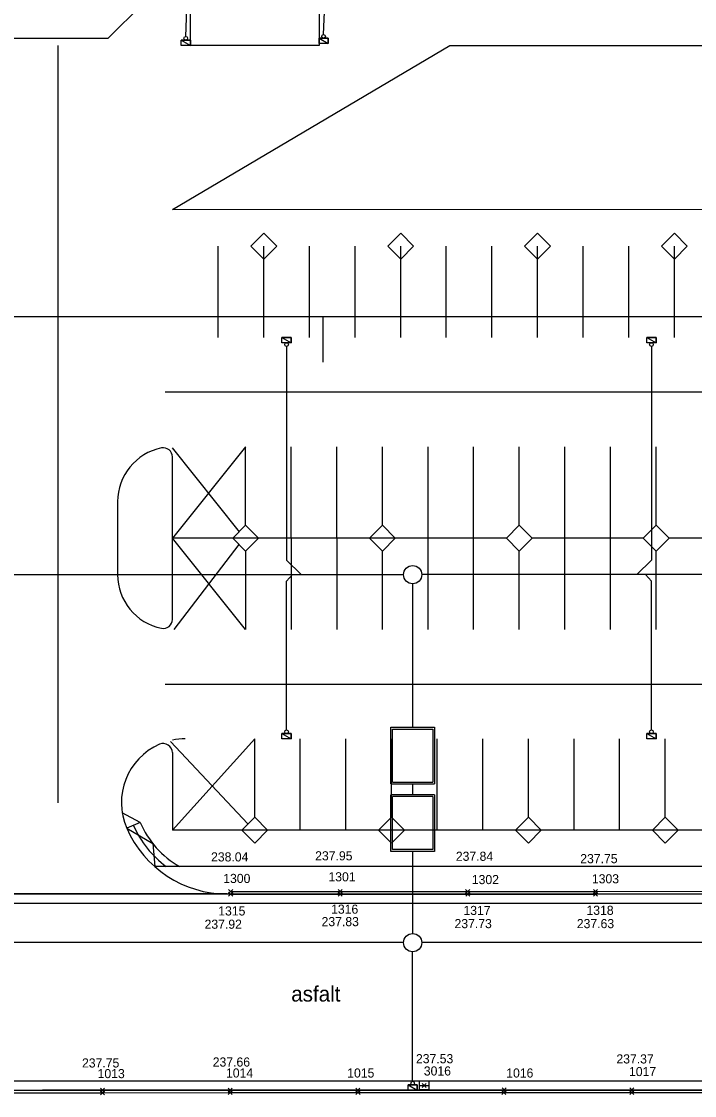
# Model space of a CAD drawing. Extents: x -264205 to -263615, y -1242401 to -1242031.
# Drawn here: x -263925.3 to -263888.5, y -1242312.5 to -1242253.7 of the extents above; entities that cross this region are included whole.
import ezdxf

# ---------------------------------------------------------------- set-up
doc = ezdxf.new("R2010")
doc.units = 0
for name, color, linetype in [('BODY_SYMBOL A CISLO_2-1', 7, 'Continuous'), ('BODY_VYSKA_2-1', 7, 'Continuous'), ('KOORDINACNA_SITUACIA_DSP', 7, 'Continuous'), ('POPIS', 7, 'Continuous'), ('PROJEKT_DRS_TDZ_VODOROVNE', 7, 'Continuous'), ('RAM_NA_TLAC_1-250_SITUACIA_2-1', 7, 'Continuous'), ('ROZHRANIE_SO_20-1_a_20-2', 7, 'Continuous'), ('SO_20-1_OBRUBNIKY_DOLNA_HRANA', 7, 'Continuous'), ('SO_20-1_OBRUBNIKY_HORNA_HRANA', 7, 'Continuous'), ('SO_20-1_UV', 7, 'Continuous')]:
    doc.layers.add(name, color=color, linetype=linetype)

msp = doc.modelspace()

# ---------------------------------------------------------------- linework, layer by layer
at = {"layer": 'BODY_SYMBOL A CISLO_2-1'}
for p, q in [((-263913.995, -1242301.454), (-263913.774, -1242301.234)), ((-263913.774, -1242301.454), (-263913.995, -1242301.234)), ((-263913.995, -1242301.6), (-263913.774, -1242301.379)), ((-263913.774, -1242301.6), (-263913.995, -1242301.379)), ((-263908.003, -1242301.454), (-263907.782, -1242301.232)), ((-263907.782, -1242301.454), (-263908.003, -1242301.232)), ((-263908.003, -1242301.6), (-263907.782, -1242301.379)), ((-263907.782, -1242301.6), (-263908.003, -1242301.379)), ((-263901.007, -1242301.454), (-263900.785, -1242301.234)), ((-263900.785, -1242301.454), (-263901.007, -1242301.234)), ((-263901.001, -1242301.599), (-263900.78, -1242301.377)), ((-263900.78, -1242301.599), (-263901.001, -1242301.377)), ((-263894.008, -1242301.593), (-263893.787, -1242301.373)), ((-263893.787, -1242301.593), (-263894.008, -1242301.373)), ((-263894.006, -1242301.448), (-263893.785, -1242301.228)), ((-263893.785, -1242301.448), (-263894.006, -1242301.228)), ((-263903.389, -1242312.082), (-263903.168, -1242311.86)), ((-263903.168, -1242312.082), (-263903.389, -1242311.86)), ((-263921.02, -1242312.345), (-263920.799, -1242312.123)), ((-263920.799, -1242312.345), (-263921.02, -1242312.123)), ((-263921.019, -1242312.488), (-263920.799, -1242312.268)), ((-263920.799, -1242312.488), (-263921.019, -1242312.268)), ((-263914.025, -1242312.336), (-263913.804, -1242312.115)), ((-263913.804, -1242312.336), (-263914.025, -1242312.115)), ((-263914.02, -1242312.475), (-263913.799, -1242312.255)), ((-263913.799, -1242312.475), (-263914.02, -1242312.255)), ((-263907.023, -1242312.338), (-263906.802, -1242312.117)), ((-263906.802, -1242312.338), (-263907.023, -1242312.117)), ((-263907.018, -1242312.468), (-263906.796, -1242312.248)), ((-263906.796, -1242312.468), (-263907.018, -1242312.248)), ((-263899.02, -1242312.468), (-263898.799, -1242312.247)), ((-263898.799, -1242312.468), (-263899.02, -1242312.247)), ((-263899.007, -1242312.319), (-263898.785, -1242312.097)), ((-263898.785, -1242312.319), (-263899.007, -1242312.097)), ((-263892.013, -1242312.465), (-263891.791, -1242312.244)), ((-263891.791, -1242312.465), (-263892.013, -1242312.244)), ((-263892.011, -1242312.319), (-263891.79, -1242312.099)), ((-263891.79, -1242312.319), (-263892.011, -1242312.099))]:
    msp.add_line(p, q, dxfattribs=at)
at = {"layer": 'KOORDINACNA_SITUACIA_DSP'}
for p, q in [((-263916.093, -1242254.982), (-263916.093, -1242250.458)), ((-263909.043, -1242250.458), (-263909.043, -1242254.982)), ((-263916.339, -1242254.492), (-263916.265, -1242252.443)), ((-263920.595, -1242254.592), (-263918.723, -1242252.72)), ((-263908.789, -1242254.387), (-263908.729, -1242252.715)), ((-263929.73, -1242254.592), (-263920.595, -1242254.592)), ((-263916.593, -1242254.692), (-263916.093, -1242254.692)), ((-263916.593, -1242254.982), (-263916.593, -1242254.692)), ((-263916.593, -1242254.692), (-263916.093, -1242254.982)), ((-263916.593, -1242254.692), (-263916.093, -1242254.982)), ((-263916.093, -1242254.692), (-263916.593, -1242254.692)), ((-263916.093, -1242254.982), (-263916.593, -1242254.982)), ((-263916.093, -1242254.692), (-263916.093, -1242254.982)), ((-263916.093, -1242254.982), (-263916.093, -1242254.692)), ((-263909.043, -1242254.982), (-263916.093, -1242254.982)), ((-263909.043, -1242254.587), (-263908.543, -1242254.587)), ((-263909.043, -1242254.877), (-263909.043, -1242254.587)), ((-263909.043, -1242254.587), (-263908.543, -1242254.877)), ((-263909.043, -1242254.587), (-263908.543, -1242254.877)), ((-263908.543, -1242254.587), (-263909.043, -1242254.587)), ((-263908.543, -1242254.877), (-263909.043, -1242254.877)), ((-263908.543, -1242254.587), (-263908.543, -1242254.877)), ((-263908.543, -1242254.877), (-263908.543, -1242254.587)), ((-263911.074, -1242270.983), (-263910.574, -1242270.983)), ((-263911.074, -1242271.273), (-263911.074, -1242270.983)), ((-263911.074, -1242270.983), (-263910.574, -1242271.273)), ((-263911.074, -1242270.983), (-263910.574, -1242271.273)), ((-263910.574, -1242270.983), (-263911.074, -1242270.983)), ((-263910.574, -1242271.273), (-263911.074, -1242271.273)), ((-263910.574, -1242270.983), (-263910.574, -1242271.273)), ((-263910.574, -1242271.273), (-263910.574, -1242270.983)), ((-263891.074, -1242270.983), (-263890.574, -1242270.983)), ((-263891.074, -1242271.273), (-263891.074, -1242270.983)), ((-263891.074, -1242270.983), (-263890.574, -1242271.273)), ((-263891.074, -1242270.983), (-263890.574, -1242271.273)), ((-263890.574, -1242270.983), (-263891.074, -1242270.983)), ((-263890.574, -1242271.273), (-263891.074, -1242271.273)), ((-263890.574, -1242270.983), (-263890.574, -1242271.273)), ((-263890.574, -1242271.273), (-263890.574, -1242270.983)), ((-263910.824, -1242271.473), (-263910.824, -1242283.187)), ((-263890.824, -1242271.473), (-263890.824, -1242283.187)), ((-263917.08, -1242286.432), (-263917.08, -1242277.533)), ((-263920.08, -1242279.982), (-263920.08, -1242283.982)), ((-263910.824, -1242283.187), (-263910.029, -1242283.982)), ((-263890.824, -1242283.187), (-263891.619, -1242283.982)), ((-263946.608, -1242283.982), (-263908.955, -1242283.982)), ((-263946.608, -1242283.982), (-263904.413, -1242283.982)), ((-263910.824, -1242284.343), (-263910.499, -1242283.982)), ((-263910.824, -1242292.492), (-263910.824, -1242284.343)), ((-263871.324, -1242283.982), (-263903.413, -1242283.982)), ((-263890.824, -1242284.343), (-263891.149, -1242283.982)), ((-263890.824, -1242292.492), (-263890.824, -1242284.343)), ((-263903.913, -1242284.482), (-263903.913, -1242292.347)), ((-263905.113, -1242292.347), (-263902.713, -1242292.347)), ((-263905.113, -1242295.447), (-263905.113, -1242292.347)), ((-263905.013, -1242292.447), (-263902.813, -1242292.447)), ((-263905.013, -1242295.347), (-263905.013, -1242292.447)), ((-263902.813, -1242292.447), (-263902.813, -1242295.347)), ((-263902.713, -1242292.347), (-263902.713, -1242295.447)), ((-263911.074, -1242292.692), (-263910.574, -1242292.692)), ((-263911.074, -1242292.982), (-263911.074, -1242292.692)), ((-263911.074, -1242292.692), (-263910.574, -1242292.982)), ((-263911.074, -1242292.692), (-263910.574, -1242292.982)), ((-263910.574, -1242292.692), (-263911.074, -1242292.692)), ((-263910.574, -1242292.982), (-263911.074, -1242292.982)), ((-263910.574, -1242292.692), (-263910.574, -1242292.982)), ((-263910.574, -1242292.982), (-263910.574, -1242292.692)), ((-263891.074, -1242292.693), (-263890.574, -1242292.693)), ((-263891.074, -1242292.983), (-263891.074, -1242292.693)), ((-263891.074, -1242292.693), (-263890.574, -1242292.983)), ((-263891.074, -1242292.693), (-263890.574, -1242292.983)), ((-263890.574, -1242292.693), (-263891.074, -1242292.693)), ((-263890.574, -1242292.983), (-263891.074, -1242292.983)), ((-263890.574, -1242292.693), (-263890.574, -1242292.983)), ((-263890.574, -1242292.983), (-263890.574, -1242292.693)), ((-263917.08, -1242293.737), (-263917.08, -1242297.982)), ((-263905.113, -1242295.447), (-263902.713, -1242295.447)), ((-263905.013, -1242295.347), (-263902.813, -1242295.347)), ((-263903.913, -1242295.447), (-263903.913, -1242296.047)), ((-263905.113, -1242299.147), (-263905.113, -1242296.047)), ((-263902.713, -1242296.047), (-263905.113, -1242296.047)), ((-263902.813, -1242296.147), (-263905.013, -1242296.147)), ((-263905.013, -1242299.047), (-263905.013, -1242296.147)), ((-263902.813, -1242296.147), (-263902.813, -1242299.047)), ((-263902.713, -1242296.047), (-263902.713, -1242299.147)), ((-263918.846, -1242297.562), (-263919.828, -1242297.035)), ((-263918.846, -1242297.562), (-263919.579, -1242297.882)), ((-263815.601, -1242297.982), (-263917.08, -1242297.982)), ((-263902.813, -1242299.047), (-263905.013, -1242299.047)), ((-263902.713, -1242299.147), (-263905.113, -1242299.147)), ((-263903.913, -1242299.147), (-263903.913, -1242303.647)), ((-263816.308, -1242299.982), (-263918.049, -1242299.982)), ((-263914.08, -1242301.482), (-263815.822, -1242301.482)), ((-263904.413, -1242304.147), (-263953.413, -1242304.147)), ((-263854.415, -1242304.147), (-263903.413, -1242304.147)), ((-263903.913, -1242311.742), (-263903.913, -1242304.647)), ((-263904.163, -1242311.942), (-263903.663, -1242311.942)), ((-263904.163, -1242312.232), (-263904.163, -1242311.942)), ((-263904.163, -1242311.942), (-263903.663, -1242312.232)), ((-263904.163, -1242311.942), (-263903.663, -1242312.232)), ((-263903.663, -1242311.942), (-263904.163, -1242311.942)), ((-263903.663, -1242311.942), (-263903.663, -1242312.232)), ((-263903.663, -1242312.232), (-263903.663, -1242311.942)), ((-263980.94, -1242312.232), (-263857.327, -1242312.232)), ((-263842.601, -1242312.24), (-263924.192, -1242312.232)), ((-263903.663, -1242312.232), (-263904.163, -1242312.232))]:
    msp.add_line(p, q, dxfattribs=at)
for points in [[(-263854.468, -1242263.985), (-263917.08, -1242263.982), (-263901.868, -1242254.982), (-263854.468, -1242254.985), (-263854.468, -1242263.985)], [(-263919.579, -1242297.882), (-263918.155, -1242298.713), (-263918.049, -1242299.982)]]:
    msp.add_lwpolyline(points, dxfattribs=at)
for points in [[(-263912.068, -1242265.279), (-263911.361, -1242265.986), (-263912.068, -1242266.693), (-263912.775, -1242265.986)], [(-263904.568, -1242265.279), (-263903.861, -1242265.986), (-263904.568, -1242266.693), (-263905.275, -1242265.986)], [(-263897.068, -1242265.279), (-263896.361, -1242265.986), (-263897.068, -1242266.693), (-263897.775, -1242265.986)], [(-263897.068, -1242265.279), (-263896.361, -1242265.986), (-263897.068, -1242266.693), (-263897.775, -1242265.986)], [(-263889.568, -1242265.279), (-263888.861, -1242265.986), (-263889.568, -1242266.693), (-263890.275, -1242265.986)], [(-263913.068, -1242281.275), (-263912.361, -1242281.982), (-263913.068, -1242282.689), (-263913.775, -1242281.982)], [(-263905.568, -1242281.275), (-263904.861, -1242281.982), (-263905.568, -1242282.689), (-263906.275, -1242281.982)], [(-263898.068, -1242281.275), (-263897.361, -1242281.982), (-263898.068, -1242282.689), (-263898.775, -1242281.982)], [(-263890.568, -1242281.275), (-263889.861, -1242281.982), (-263890.568, -1242282.689), (-263891.275, -1242281.982)], [(-263890.568, -1242281.275), (-263889.861, -1242281.982), (-263890.568, -1242282.689), (-263891.275, -1242281.982)], [(-263912.568, -1242297.275), (-263911.861, -1242297.982), (-263912.568, -1242298.689), (-263913.275, -1242297.982)], [(-263905.068, -1242297.275), (-263904.361, -1242297.982), (-263905.068, -1242298.689), (-263905.775, -1242297.982)], [(-263897.568, -1242297.275), (-263896.861, -1242297.982), (-263897.568, -1242298.689), (-263898.275, -1242297.982)], [(-263890.068, -1242297.275), (-263889.361, -1242297.982), (-263890.068, -1242298.689), (-263890.775, -1242297.982)], [(-263890.068, -1242297.275), (-263889.361, -1242297.982), (-263890.068, -1242298.689), (-263890.775, -1242297.982)]]:
    msp.add_lwpolyline(points, close=True, dxfattribs=at)
for centre, radius in [((-263908.793, -1242254.487), 0.1), ((-263916.343, -1242254.592), 0.1), ((-263910.824, -1242271.373), 0.1), ((-263890.824, -1242271.373), 0.1), ((-263903.913, -1242283.982), 0.5), ((-263910.824, -1242292.592), 0.1), ((-263890.824, -1242292.592), 0.1), ((-263903.913, -1242304.147), 0.5), ((-263903.913, -1242311.842), 0.1)]:
    msp.add_circle(centre, radius, dxfattribs=at)
for centre, radius, start, end in [((-263917.08, -1242279.982), 3, 101.53696, 180), ((-263917.58, -1242277.533), 0.5, 0, 101.53696), ((-263917.08, -1242283.982), 3, 180, 258.46304), ((-263917.58, -1242286.432), 0.5, 258.46304, 0), ((-263917.58, -1242293.737), 0.5, 0, 113.75985), ((-263916.372, -1242296.482), 3.5, 113.75985, 203.57818), ((-263914.08, -1242295.482), 6, 203.57818, 270), ((-263914.08, -1242295.482), 5.6, 203.57818, 233.47251), ((-263914.08, -1242295.482), 5.2, 203.57818, 239.92665)]:
    msp.add_arc(centre, radius, start, end, dxfattribs=at)
at = {"layer": 'PROJEKT_DRS_TDZ_VODOROVNE'}
for p, q in [((-263923.33, -1242296.482), (-263923.33, -1242254.982)), ((-263914.568, -1242270.982), (-263914.568, -1242265.982)), ((-263912.068, -1242270.982), (-263912.068, -1242265.982)), ((-263909.568, -1242270.982), (-263909.568, -1242265.982)), ((-263907.068, -1242270.982), (-263907.068, -1242265.982)), ((-263904.568, -1242270.982), (-263904.568, -1242265.982)), ((-263902.068, -1242270.982), (-263902.068, -1242265.982)), ((-263899.568, -1242270.982), (-263899.568, -1242265.982)), ((-263897.068, -1242270.982), (-263897.068, -1242265.982)), ((-263894.568, -1242270.982), (-263894.568, -1242265.982)), ((-263892.068, -1242270.982), (-263892.068, -1242265.982)), ((-263889.568, -1242270.982), (-263889.568, -1242265.982)), ((-263817.068, -1242273.982), (-263917.477, -1242273.982)), ((-263917.087, -1242277.034), (-263913.421, -1242281.629)), ((-263913.068, -1242276.982), (-263917.08, -1242281.982)), ((-263913.068, -1242281.275), (-263913.068, -1242276.982)), ((-263910.568, -1242281.982), (-263910.568, -1242276.982)), ((-263908.068, -1242281.982), (-263908.068, -1242276.982)), ((-263905.568, -1242281.275), (-263905.568, -1242276.982)), ((-263903.068, -1242281.982), (-263903.068, -1242276.982)), ((-263900.568, -1242281.982), (-263900.568, -1242276.982)), ((-263898.068, -1242281.275), (-263898.068, -1242276.982)), ((-263895.568, -1242281.982), (-263895.568, -1242276.982)), ((-263893.068, -1242281.982), (-263893.068, -1242276.982)), ((-263890.568, -1242281.275), (-263890.568, -1242276.982)), ((-263898.775, -1242281.982), (-263917.08, -1242281.982)), ((-263913.068, -1242286.982), (-263917.08, -1242281.982)), ((-263910.568, -1242281.982), (-263910.568, -1242286.982)), ((-263908.068, -1242281.982), (-263908.068, -1242286.982)), ((-263903.068, -1242286.982), (-263903.068, -1242281.982)), ((-263900.568, -1242286.982), (-263900.568, -1242281.982)), ((-263891.275, -1242281.982), (-263897.361, -1242281.982)), ((-263895.568, -1242286.982), (-263895.568, -1242281.982)), ((-263893.068, -1242286.982), (-263893.068, -1242281.982)), ((-263883.775, -1242281.982), (-263889.861, -1242281.982)), ((-263916.984, -1242286.982), (-263913.421, -1242282.336)), ((-263913.068, -1242282.689), (-263913.068, -1242286.982)), ((-263905.568, -1242286.982), (-263905.568, -1242282.689)), ((-263898.068, -1242286.982), (-263898.068, -1242282.689)), ((-263890.568, -1242286.982), (-263890.568, -1242282.689)), ((-263819.531, -1242289.994), (-263917.477, -1242289.994)), ((-263917.187, -1242293.118), (-263912.937, -1242297.644)), ((-263917.08, -1242297.982), (-263912.568, -1242292.982)), ((-263912.568, -1242297.275), (-263912.568, -1242292.982)), ((-263910.068, -1242297.982), (-263910.068, -1242292.982)), ((-263907.568, -1242297.982), (-263907.568, -1242292.982)), ((-263905.068, -1242297.275), (-263905.068, -1242292.982)), ((-263902.568, -1242297.982), (-263902.568, -1242292.982)), ((-263900.068, -1242297.982), (-263900.068, -1242292.982)), ((-263897.568, -1242297.275), (-263897.568, -1242292.982)), ((-263895.068, -1242297.982), (-263895.068, -1242292.982)), ((-263892.568, -1242297.982), (-263892.568, -1242292.982)), ((-263890.068, -1242297.275), (-263890.068, -1242292.982)), ((-263914.08, -1242301.482), (-263932.58, -1242301.482)), ((-263932.58, -1242301.982), (-263913.841, -1242301.982)), ((-263913.857, -1242301.982), (-263816.374, -1242301.982)), ((-263842.661, -1242311.732), (-263980.94, -1242311.732))]:
    msp.add_line(p, q, dxfattribs=at)
msp.add_arc((-263916.372, -1242296.482), 3.5, 90, 101.68256, dxfattribs=at)
at = {"layer": 'RAM_NA_TLAC_1-250_SITUACIA_2-1'}
msp.add_line((-263908.833, -1242269.835), (-263908.833, -1242272.335), dxfattribs=at)
msp.add_lwpolyline([(-264151.333, -1242269.835), (-263718.833, -1242269.835), (-263718.833, -1242344.085), (-264151.333, -1242344.085)], close=True, dxfattribs=at)
at = {"layer": 'ROZHRANIE_SO_20-1_a_20-2'}
msp.add_line((-263931.888, -1242301.474), (-263913.884, -1242301.489), dxfattribs=at)
at = {"layer": 'SO_20-1_OBRUBNIKY_DOLNA_HRANA'}
for points in [[(-263913.884, -1242301.489), (-263907.893, -1242301.489), (-263900.89, -1242301.488), (-263893.898, -1242301.483), (-263886.917, -1242301.473), (-263879.922, -1242301.465), (-263872.91, -1242301.469), (-263865.929, -1242301.465), (-263859.932, -1242301.473), (-263850.941, -1242301.471), (-263843.947, -1242301.471), (-263836.942, -1242301.481), (-263829.943, -1242301.484), (-263823.945, -1242301.487), (-263818.452, -1242301.495), (-263816.42, -1242301.504)], [(-263927.909, -1242312.235), (-263920.91, -1242312.234), (-263913.915, -1242312.225), (-263906.912, -1242312.227), (-263898.896, -1242312.208), (-263891.9, -1242312.209), (-263883.905, -1242312.21), (-263878.731, -1242312.212), (-263870.923, -1242312.226), (-263863.907, -1242312.232), (-263855.93, -1242312.232)]]:
    msp.add_lwpolyline(points, dxfattribs=at)
at = {"layer": 'SO_20-1_OBRUBNIKY_HORNA_HRANA'}
for points in [[(-263913.884, -1242301.344), (-263907.893, -1242301.343), (-263900.896, -1242301.344), (-263893.895, -1242301.338), (-263886.916, -1242301.328), (-263879.921, -1242301.324), (-263872.911, -1242301.324), (-263865.928, -1242301.325), (-263859.931, -1242301.327), (-263850.935, -1242301.324), (-263843.941, -1242301.331), (-263836.939, -1242301.332), (-263829.941, -1242301.342), (-263823.94, -1242301.343), (-263818.456, -1242301.352), (-263816.413, -1242301.358)], [(-263927.907, -1242312.381), (-263920.909, -1242312.378), (-263913.91, -1242312.365), (-263906.907, -1242312.358), (-263898.91, -1242312.357), (-263891.902, -1242312.354), (-263883.907, -1242312.356), (-263878.731, -1242312.358), (-263870.924, -1242312.368), (-263863.913, -1242312.368), (-263855.926, -1242312.378)]]:
    msp.add_lwpolyline(points, dxfattribs=at)
at = {"layer": 'SO_20-1_UV'}
msp.add_line((-263903.279, -1242311.971), (-263903.279, -1242311.971), dxfattribs=at)
msp.add_lwpolyline([(-263903.529, -1242311.971), (-263903.529, -1242311.721), (-263903.029, -1242311.721), (-263903.029, -1242312.221), (-263903.529, -1242312.221), (-263903.529, -1242311.971), (-263903.029, -1242311.971)], dxfattribs=at)

# ---------------------------------------------------------------- texts
at = {"layer": 'BODY_SYMBOL A CISLO_2-1'}
for s, p in [('1301', (-263908.527, -1242300.791)), ('1300', (-263914.292, -1242300.88)), ('1302', (-263900.669, -1242300.942)), ('1303', (-263894.088, -1242300.9)), ('1316', (-263908.381, -1242302.564)), ('1315', (-263914.565, -1242302.661)), ('1317', (-263901.128, -1242302.635)), ('1318', (-263894.386, -1242302.625)), ('1013', (-263921.177, -1242311.574)), ('1014', (-263914.141, -1242311.539)), ('1015', (-263907.498, -1242311.541)), ('3016', (-263903.3, -1242311.429)), ('1016', (-263898.783, -1242311.541)), ('1017', (-263892.054, -1242311.462))]:
    msp.add_text(s, height=0.5, dxfattribs=at).set_placement(p)
at = {"layer": 'BODY_VYSKA_2-1'}
for s, p in [('238.04', (-263914.96, -1242299.699)), ('237.95', (-263909.254, -1242299.641)), ('237.84', (-263901.545, -1242299.665)), ('237.75', (-263894.727, -1242299.795)), ('237.92', (-263915.315, -1242303.387)), ('237.83', (-263908.903, -1242303.246)), ('237.73', (-263901.617, -1242303.355)), ('237.63', (-263894.915, -1242303.355)), ('237.53', (-263903.731, -1242310.758)), ('237.37', (-263892.745, -1242310.769)), ('237.75', (-263922.032, -1242310.99)), ('237.66', (-263914.868, -1242310.94))]:
    msp.add_text(s, height=0.5, dxfattribs=at).set_placement(p)
at = {"layer": 'POPIS'}
msp.add_text('asfalt', height=0.8438, dxfattribs=at).set_placement((-263910.567, -1242307.377))

doc.saveas('drawing.dxf')
